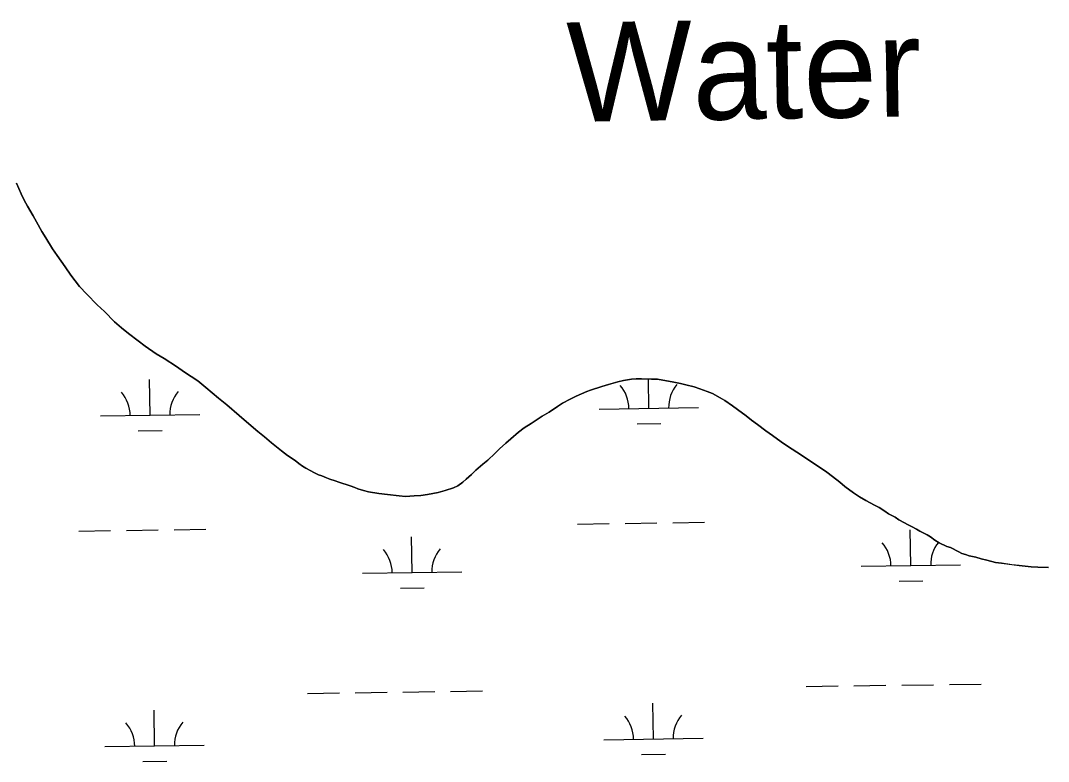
# Model space of a CAD drawing. Extents: x 3767014 to 3805179, y 361544 to 387384.
# Drawn here: x 3780033 to 3781068, y 370786 to 371531 of the extents above; entities that cross this region are included whole.
import ezdxf

# ---------------------------------------------------------------- set-up
doc = ezdxf.new("R2010")
doc.units = 0
for name, color, linetype in [('V-RIVR-IDEN', 7, 'Continuous'), ('V-TOPO-SHOR', 7, 'Continuous'), ('V-WETL-SWMP', 7, 'Continuous')]:
    doc.layers.add(name, color=color, linetype=linetype)

msp = doc.modelspace()

# ---------------------------------------------------------------- linework, layer by layer
at = {"layer": 'V-TOPO-SHOR'}
for points in [[(3780336.701, 371073.295), (3780333.326, 371074.309), (3780328.437, 371076.599), (3780325.388, 371078.225), (3780320.507, 371080.824), (3780317.163, 371083.072), (3780313.52, 371085.641), (3780309.573, 371088.524), (3780301.977, 371093.669), (3780295.915, 371098.461), (3780285.919, 371106.448), (3780278.964, 371112.502), (3780272.3, 371117.929), (3780260.798, 371127.502), (3780253.231, 371133.881), (3780240.832, 371144.711), (3780232.656, 371151.416), (3780219.951, 371162.254), (3780211.767, 371168.65), (3780198.393, 371177.651), (3780190.185, 371183.119), (3780178.024, 371191.162), (3780169.801, 371196.011), (3780158.869, 371203.714), (3780151.586, 371209.157), (3780141.883, 371216.518), (3780134.92, 371222.263), (3780127.963, 371228.317), (3780117.712, 371238.475), (3780110.462, 371245.153), (3780099.919, 371255.938), (3780092.694, 371263.544), (3780084.027, 371275.208), (3780078.362, 371283.393), (3780070.307, 371294.731), (3780065.538, 371301.655), (3780058.709, 371312.653), (3780054.851, 371318.936), (3780049.536, 371328.658), (3780045.987, 371334.933), (3780040.355, 371344.354), (3780037.115, 371350.621), (3780033.875, 371356.89), (3780029.202, 371367.521)], [(3780969.002, 371001.06), (3780965.318, 371002.082), (3780957.681, 371005.68), (3780953.427, 371008.572), (3780948.871, 371011.781), (3780945.52, 371013.725), (3780940.949, 371016.316), (3780938.201, 371017.622), (3780934.848, 371019.564), (3780930.578, 371021.837), (3780925.999, 371024.121), (3780922.957, 371026.054), (3780917.157, 371028.987), (3780913.514, 371031.553), (3780906.803, 371035.127), (3780903.159, 371037.695), (3780897.376, 371041.244), (3780892.805, 371043.835), (3780883.955, 371048.392), (3780877.561, 371052.266), (3780871.477, 371056.133), (3780862.674, 371062.543), (3780857.841, 371066.998), (3780850.563, 371072.439), (3780844.802, 371076.916), (3780836.294, 371082.702), (3780830.511, 371086.253), (3780821.092, 371092.677), (3780814.397, 371096.87), (3780804.97, 371102.987), (3780798.9, 371107.472), (3780790.097, 371113.882), (3780783.413, 371118.384), (3780774.92, 371124.786), (3780768.851, 371129.271), (3780763.391, 371133.431), (3780754.898, 371139.833), (3780749.742, 371143.677), (3780742.152, 371149.129), (3780737.271, 371151.727), (3780729.651, 371155.942), (3780724.137, 371157.939), (3780716.783, 371160.601), (3780711.27, 371162.598), (3780702.975, 371164.669), (3780697.446, 371166.047), (3780689.141, 371167.806), (3780683.294, 371168.886), (3780674.367, 371170.352), (3780668.186, 371170.51), (3780658.298, 371170.766), (3780652.736, 371170.909), (3780648.085, 371170.409), (3780640.014, 371169.072), (3780634.41, 371167.669), (3780625.07, 371165.128), (3780618.217, 371163.139), (3780606.99, 371159.407), (3780603.242, 371157.957), (3780592.609, 371153.286), (3780586.348, 371150.353), (3780578.822, 371146.218), (3780573.792, 371142.948), (3780565.297, 371137.291), (3780558.389, 371133.14), (3780547.074, 371126.011), (3780540.155, 371121.55), (3780534.474, 371117.059), (3780526.575, 371110.46), (3780521.83, 371106.254), (3780515.182, 371100.241), (3780510.738, 371095.717), (3780503.455, 371089.102), (3780498.401, 371084.903), (3780491.444, 371078.899), (3780487.315, 371074.676), (3780481.626, 371069.875), (3780478.455, 371066.864), (3780473.417, 371063.285), (3780469.034, 371061.232), (3780460.613, 371058.357), (3780453.451, 371056.377), (3780442.89, 371054.484), (3780436.06, 371053.423), (3780429.555, 371052.973), (3780420.579, 371052.586), (3780414.406, 371053.053), (3780402.69, 371054.282), (3780394.061, 371055.433), (3780383.596, 371057.247), (3780378.374, 371058.617), (3780372.852, 371060.307), (3780369.795, 371061.622), (3780365.199, 371063.287), (3780362.133, 371064.292), (3780356.61, 371065.98), (3780353.544, 371066.987), (3780349.868, 371068.319), (3780344.655, 371069.998), (3780341.288, 371071.323), (3780336.701, 371073.295)], [(3781067.855, 370981.049), (3781057.042, 370981.328), (3781050.251, 370981.811), (3781038.225, 370983.048), (3781030.823, 370983.857), (3781020.35, 370985.364), (3781014.495, 370986.132), (3781005.59, 370988.526), (3781000.052, 370989.598), (3780994.531, 370991.285), (3780988.073, 370992.688), (3780984.397, 370994.019), (3780980.713, 370995.041), (3780977.663, 370996.665), (3780969.002, 371001.06)]]:
    msp.add_lwpolyline(points, dxfattribs=at)
at = {"layer": 'V-WETL-SWMP'}
for p, q in [((3780163.67, 371134.14), (3780163.17, 371170.137)), ((3780665.529, 371141.112), (3780665.12, 371170.589)), ((3780615.534, 371140.417), (3780715.524, 371141.806)), ((3780113.674, 371133.446), (3780213.665, 371134.835)), ((3780653.745, 371125.515), (3780677.742, 371125.849)), ((3780151.885, 371118.544), (3780175.883, 371118.877)), ((3780091.872, 371017.7), (3780123.869, 371018.144)), ((3780139.867, 371018.366), (3780171.864, 371018.811)), ((3780187.863, 371019.033), (3780219.86, 371019.478)), ((3780593.732, 371024.671), (3780625.729, 371025.116)), ((3780641.727, 371025.338), (3780673.724, 371025.782)), ((3780689.722, 371026.005), (3780721.719, 371026.449)), ((3780929.188, 370982.897), (3780928.688, 371018.893)), ((3780427.329, 370975.925), (3780426.829, 371011.922)), ((3780377.334, 370975.231), (3780477.324, 370976.62)), ((3780879.193, 370982.202), (3780979.183, 370983.591)), ((3780917.404, 370967.3), (3780941.401, 370967.634)), ((3780415.544, 370960.329), (3780439.542, 370960.662)), ((3780872.018, 370862.02), (3780904.015, 370862.464)), ((3780920.013, 370862.687), (3780952.01, 370863.131)), ((3780968.008, 370863.353), (3781000.005, 370863.798)), ((3780322.163, 370854.382), (3780354.16, 370854.826)), ((3780370.158, 370855.048), (3780402.155, 370855.493)), ((3780418.154, 370855.715), (3780450.15, 370856.16)), ((3780466.149, 370856.382), (3780498.146, 370856.826)), ((3780824.022, 370861.353), (3780856.019, 370861.798)), ((3780670.15, 370808.469), (3780669.65, 370844.465)), ((3780168.29, 370801.497), (3780167.79, 370837.494)), ((3780118.295, 370800.803), (3780218.286, 370802.192)), ((3780620.155, 370807.774), (3780720.145, 370809.163)), ((3780658.366, 370792.873), (3780682.363, 370793.206)), ((3780156.506, 370785.901), (3780180.504, 370786.234))]:
    msp.add_line(p, q, dxfattribs=at)
for points in [[(3780029.201, 371367.522), (3780033.875, 371356.889), (3780037.115, 371350.622), (3780040.355, 371344.355), (3780045.987, 371334.934), (3780049.536, 371328.659), (3780054.851, 371318.937), (3780058.709, 371312.654), (3780065.538, 371301.656), (3780070.307, 371294.731), (3780078.363, 371283.393), (3780084.027, 371275.208), (3780092.694, 371263.545), (3780099.919, 371255.938), (3780110.463, 371245.154), (3780117.712, 371238.474), (3780127.963, 371228.316), (3780134.919, 371222.263), (3780141.883, 371216.518), (3780151.587, 371209.157), (3780158.868, 371203.713), (3780169.801, 371196.011), (3780178.024, 371191.162), (3780190.185, 371183.119), (3780198.393, 371177.651), (3780211.766, 371168.65), (3780219.95, 371162.255), (3780232.657, 371151.416), (3780240.833, 371144.712), (3780253.231, 371133.881), (3780260.797, 371127.502), (3780272.3, 371117.93), (3780278.963, 371112.502), (3780285.918, 371106.449), (3780295.916, 371098.461), (3780301.977, 371093.668), (3780309.574, 371088.525), (3780313.52, 371085.641), (3780317.164, 371083.073), (3780320.507, 371080.823), (3780325.387, 371078.224), (3780328.438, 371076.599), (3780333.326, 371074.309), (3780336.701, 371073.295)], [(3780336.701, 371073.295), (3780341.288, 371071.322), (3780344.655, 371069.998), (3780349.868, 371068.318), (3780353.544, 371066.987), (3780356.61, 371065.98), (3780362.132, 371064.292), (3780365.199, 371063.286), (3780369.794, 371061.621), (3780372.852, 371060.306), (3780378.374, 371058.618), (3780383.595, 371057.247), (3780394.061, 371055.432), (3780402.689, 371054.282), (3780414.407, 371053.053), (3780420.578, 371052.585), (3780429.555, 371052.972), (3780436.06, 371053.423), (3780442.889, 371054.484), (3780453.451, 371056.377), (3780460.613, 371058.357), (3780469.035, 371061.232), (3780473.417, 371063.284), (3780478.456, 371066.865), (3780481.626, 371069.875), (3780487.315, 371074.676), (3780491.443, 371078.898), (3780498.4, 371084.903), (3780503.455, 371089.102), (3780510.737, 371095.717), (3780515.182, 371100.24), (3780521.829, 371106.253), (3780526.576, 371110.46), (3780534.475, 371117.059), (3780540.156, 371121.551), (3780547.073, 371126.01), (3780558.388, 371133.14), (3780565.297, 371137.291), (3780573.791, 371142.947), (3780578.822, 371146.219), (3780586.349, 371150.354), (3780592.609, 371153.285), (3780603.242, 371157.958), (3780606.989, 371159.408), (3780618.216, 371163.139), (3780625.07, 371165.127), (3780634.411, 371167.669), (3780640.013, 371169.071), (3780648.086, 371170.409), (3780652.737, 371170.908), (3780658.299, 371170.765), (3780668.186, 371170.51), (3780674.366, 371170.351), (3780683.295, 371168.885), (3780689.142, 371167.807), (3780697.445, 371166.047), (3780702.975, 371164.668), (3780711.27, 371162.599), (3780716.784, 371160.602), (3780724.137, 371157.94), (3780729.651, 371155.942), (3780737.272, 371151.727), (3780742.152, 371149.128), (3780749.742, 371143.676), (3780754.899, 371139.833), (3780763.392, 371133.431), (3780768.851, 371129.271), (3780774.919, 371124.786), (3780783.412, 371118.383), (3780790.098, 371113.882), (3780798.9, 371107.472), (3780804.969, 371102.987), (3780814.396, 371096.87), (3780821.091, 371092.678), (3780830.51, 371086.252), (3780836.294, 371082.702), (3780844.802, 371076.917), (3780850.562, 371072.44), (3780857.842, 371066.997), (3780862.675, 371062.544), (3780871.477, 371056.133), (3780877.561, 371052.266), (3780883.955, 371048.392), (3780892.804, 371043.835), (3780897.375, 371041.244), (3780903.159, 371037.694), (3780906.803, 371035.127), (3780913.513, 371031.553), (3780917.158, 371028.986), (3780922.957, 371026.054), (3780925.999, 371024.12), (3780930.578, 371021.838), (3780934.848, 371019.564), (3780938.2, 371017.622), (3780940.949, 371016.315), (3780945.52, 371013.724), (3780948.871, 371011.782), (3780953.427, 371008.573), (3780957.681, 371005.681), (3780965.318, 371002.083), (3780969.002, 371001.061)], [(3780969.002, 371001.061), (3780977.663, 370996.666), (3780980.713, 370995.042), (3780984.397, 370994.019), (3780988.073, 370992.688), (3780994.53, 370991.285), (3781000.052, 370989.597), (3781005.59, 370988.527), (3781014.495, 370986.133), (3781020.35, 370985.364), (3781030.824, 370983.858), (3781038.224, 370983.049), (3781050.251, 370981.812), (3781057.041, 370981.328), (3781067.856, 370981.05)]]:
    msp.add_lwpolyline(points, dxfattribs=at)
for centre, start, end in [((3780610.285, 371140.819), 0.024037, 41.567696), ((3780720.76, 371142.354), 140.024034, 181.567693), ((3780108.425, 371133.848), 0.024037, 41.567696), ((3780218.901, 371135.382), 140.024034, 181.567693), ((3780372.084, 370975.633), 0.024037, 41.567696), ((3780482.56, 370977.167), 140.024034, 181.567693), ((3780873.944, 370982.604), 0.024037, 41.567696), ((3780984.419, 370984.139), 141.26268, 181.567693), ((3780614.906, 370808.176), 0.024037, 41.567696), ((3780725.381, 370809.711), 140.024034, 181.567693), ((3780113.046, 370801.205), 0.024037, 41.567696), ((3780223.522, 370802.739), 140.024034, 181.567693)]:
    msp.add_arc(centre, 35.246, start, end, dxfattribs=at)

# ---------------------------------------------------------------- texts
at = {"layer": 'V-RIVR-IDEN'}
msp.add_text('Water', height=100, rotation=0.919589, dxfattribs=at).set_placement((3780583.817, 371429.235))

doc.saveas('drawing.dxf')
